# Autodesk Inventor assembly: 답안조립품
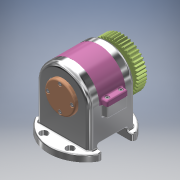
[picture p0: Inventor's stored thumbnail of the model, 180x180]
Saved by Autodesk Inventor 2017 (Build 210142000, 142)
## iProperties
Part Number: 답안조립품
Material: 일반
Document SubType Name: Assembly
Designer: MRC
Author: MRC
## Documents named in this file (21)
- C:\Users\MRC\Desktop\740804V1008\답안조립품.iam
- C:\Users\MRC\Desktop\740804V1008\본체.ipt
- C:\Users\MRC\Desktop\740804V1008\오일레스 부시 20 15.ipt
- C:\Users\MRC\Desktop\740804V1008\부시 커버.ipt
- C:\Users\MRC\Desktop\740804V1008\육각 소켓 머리 볼트 M4x10.ipt
- C:\Users\MRC\Desktop\740804V1008\링크.ipt
- C:\Users\MRC\Desktop\740804V1008\펀치.ipt
- C:\Users\MRC\Desktop\740804V1008\핀.ipt
- C:\Users\MRC\Desktop\740804V1008\E형 멈춤링 10-8.ipt
- C:\Users\MRC\Desktop\740804V1008\깊은 홈 볼 베어링 6904.ipt
- C:\Users\MRC\Desktop\740804V1008\칼라.ipt
- C:\Users\MRC\Desktop\740804V1008\편심축.ipt
- C:\Users\MRC\Desktop\740804V1008\뒷커버.ipt
- C:\Users\MRC\Desktop\740804V1008\오일실 20 32 5.ipt
- C:\Users\MRC\Desktop\740804V1008\앞커버.ipt
- C:\Users\MRC\Desktop\740804V1008\평행키 5x5x12.ipt
- C:\Users\MRC\Desktop\740804V1008\스퍼 기어.ipt
- C:\Users\MRC\Desktop\740804V1008\평와셔 M10.ipt
- C:\Users\MRC\Desktop\740804V1008\스프링 와셔 M10.ipt
- C:\Users\MRC\Desktop\740804V1008\육각 너트 M10x1.ipt
- C:\Users\MRC\Desktop\740804V1008\윗커버.ipt
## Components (2 placed, 2 different names)
1. 핀:1
2. E형 멈춤링 10-8:1
